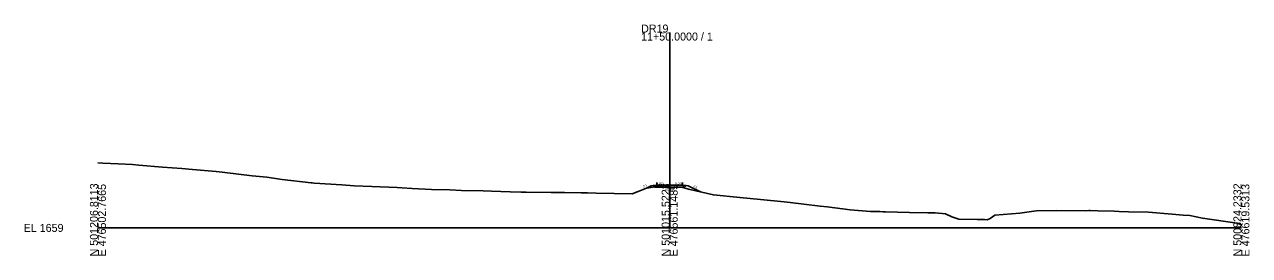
# Model space of a CAD drawing. Extents: x 79370 to 79799, y -95930 to -94349.
# Drawn here: x 79370.3 to 79798.8, y -94430.2 to -94349.2 of the extents above; entities that cross this region are included whole.
import ezdxf

# ---------------------------------------------------------------- set-up
doc = ezdxf.new("R2010")
doc.units = 0
for name, color, linetype in [('Exist Cross Section Cell', 7, 'Continuous'), ('Exist XS Center Line Elevation Label', 7, 'Continuous'), ('Exist XS Ground Line', 7, 'Continuous'), ('Prop XS Earthwork Shape', 7, 'Continuous'), ('Prop XS EOT Tick Mark', 7, 'Continuous'), ('Prop XS Finish Grade', 7, 'Continuous'), ('Prop XS Finish Grade Earthwork', 7, 'Continuous'), ('Prop XS Finish Grade Pavement', 7, 'Continuous'), ('Prop XS Pvmt Edge Slope', 7, 'Continuous'), ('Prop XS SE Text', 7, 'Continuous'), ('Prop XS Shoulder Borrow Shape', 7, 'Continuous'), ('Prop XS Side Slope Text', 7, 'Continuous'), ('Prop XS Subgrade Earthwork', 7, 'Continuous'), ('Scratch_Level_6', 7, 'Continuous')]:
    doc.layers.add(name, color=color, linetype=linetype)

msp = doc.modelspace()

# ---------------------------------------------------------------- linework, layer by layer
at = {"layer": 'Exist Cross Section Cell'}
for p, q in [((79596.01, -94420.51), (79596.01, -94352.03)), ((79396.01, -94420.51), (79596.01, -94420.51)), ((79596.01, -94420.51), (79796.01, -94420.51))]:
    msp.add_line(p, q, dxfattribs=at)
at = {"layer": 'Exist XS Ground Line'}
msp.add_lwpolyline([(79396.01, -94397.68), (79397.68, -94397.79), (79403.13, -94398.05), (79408.14, -94398.28), (79410.35, -94398.47), (79418.6, -94399.17), (79425.4, -94399.73), (79429.06, -94400), (79437.39, -94400.74), (79439.51, -94400.93), (79440.45, -94401.04), (79449.97, -94402.28), (79455.04, -94402.7), (79460.43, -94403.57), (79470.55, -94404.73), (79470.89, -94404.76), (79471.65, -94404.82), (79481.34, -94405.45), (79485.6, -94405.76), (79491.8, -94406.02), (79500.65, -94406.4), (79502.26, -94406.46), (79505.92, -94406.68), (79512.72, -94407.05), (79519.14, -94407.13), (79523.17, -94407.38), (79530.75, -94407.57), (79533.63, -94407.63), (79540.18, -94407.83), (79544.09, -94407.94), (79545.8, -94407.99), (79554.55, -94408.11), (79559.2, -94408.09), (79565, -94408.22), (79567.21, -94408.17), (79570.27, -94408.35), (79582.91, -94408.52), (79585.01, -94407.7), (79587.87, -94406.55), (79590.2, -94406.27), (79591.09, -94406.08), (79596.01, -94406.16), (79598.21, -94406.19), (79600.17, -94406.27), (79602.56, -94406.91), (79611.33, -94408.95), (79620.59, -94409.87), (79627.75, -94410.51), (79636.11, -94411.35), (79638.2, -94411.55), (79642.97, -94412.14), (79648.66, -94412.9), (79651.16, -94413.11), (79659.12, -94414.17), (79666.21, -94414.7), (79669.58, -94414.79), (79670.67, -94414.88), (79671.57, -94414.92), (79679.86, -94415.07), (79686.31, -94415.27), (79688.9, -94415.27), (79692.46, -94415.59), (79694.68, -94416.61), (79697.14, -94417.41), (79703.59, -94417.57), (79706.14, -94417.61), (79707.11, -94417.68), (79708.12, -94417.16), (79709.72, -94416.1), (79718.47, -94415.38), (79723.4, -94414.63), (79724.33, -94414.49), (79731.34, -94414.45), (79741.49, -94414.49), (79742.63, -94414.44), (79743.12, -94414.43), (79745.76, -94414.52), (79751.49, -94414.68), (79753.24, -94414.71), (79756.52, -94414.83), (79763.53, -94415.01), (79771.81, -94415.72), (79775.7, -94416), (79777.94, -94416.13), (79782.35, -94417.05), (79794.58, -94418.85), (79796.01, -94419.39)], dxfattribs=at)
at = {"layer": 'Prop XS Earthwork Shape'}
for points in [[(79590.72, -94406.16), (79590.25, -94405.69), (79589.51, -94405.74), (79587.87, -94406.55), (79590.2, -94406.27)], [(79589.51, -94405.74), (79587.87, -94406.55), (79590.2, -94406.27), (79590.72, -94406.16), (79590.25, -94405.69)], [(79600.51, -94406.25), (79601.19, -94406.27), (79601.77, -94405.69), (79602.51, -94405.74), (79606.82, -94407.9), (79602.56, -94406.91), (79600.17, -94406.27), (79599.77, -94406.25)], [(79602.51, -94405.74), (79606.82, -94407.9), (79602.56, -94406.91), (79600.17, -94406.27), (79600.17, -94406.24), (79600.51, -94406.25), (79601.19, -94406.27), (79601.77, -94405.69)], [(79590.72, -94406.16), (79591.09, -94406.08), (79591.51, -94406.08), (79591.51, -94406.25), (79590.83, -94406.27)], [(79590.83, -94406.27), (79590.72, -94406.16), (79591.09, -94406.08), (79596.01, -94406.16), (79598.21, -94406.19), (79599.77, -94406.25), (79591.51, -94406.25)]]:
    msp.add_lwpolyline(points, close=True, dxfattribs=at)
at = {"layer": 'Prop XS EOT Tick Mark'}
for p, q in [((79591.51, -94405.58), (79591.51, -94404.58)), ((79600.51, -94405.58), (79600.51, -94404.58))]:
    msp.add_line(p, q, dxfattribs=at)
at = {"layer": 'Prop XS Finish Grade'}
for p, q in [((79591.51, -94405.58), (79590.25, -94405.69)), ((79600.51, -94405.58), (79601.77, -94405.69))]:
    msp.add_line(p, q, dxfattribs=at)
at = {"layer": 'Prop XS Finish Grade Earthwork'}
for p, q in [((79590.25, -94405.69), (79589.51, -94405.74)), ((79601.77, -94405.69), (79602.51, -94405.74)), ((79589.51, -94405.74), (79587.87, -94406.55)), ((79602.51, -94405.74), (79606.82, -94407.9))]:
    msp.add_line(p, q, dxfattribs=at)
at = {"layer": 'Prop XS Finish Grade Pavement'}
for p, q in [((79591.51, -94405.58), (79596.01, -94405.49)), ((79596.01, -94405.49), (79600.51, -94405.58))]:
    msp.add_line(p, q, dxfattribs=at)
at = {"layer": 'Prop XS Pvmt Edge Slope'}
for p, q in [((79591.51, -94405.58), (79590.83, -94406.27)), ((79600.51, -94405.58), (79601.19, -94406.27))]:
    msp.add_line(p, q, dxfattribs=at)
at = {"layer": 'Prop XS Shoulder Borrow Shape'}
for points in [[(79591.51, -94405.58), (79590.83, -94406.27), (79590.25, -94405.69)], [(79601.19, -94406.27), (79601.77, -94405.69), (79600.51, -94405.58)]]:
    msp.add_lwpolyline(points, close=True, dxfattribs=at)
at = {"layer": 'Prop XS Subgrade Earthwork'}
for p, q in [((79590.83, -94406.27), (79590.25, -94405.69)), ((79601.19, -94406.27), (79601.77, -94405.69)), ((79591.51, -94406.25), (79590.83, -94406.27)), ((79600.51, -94406.25), (79591.51, -94406.25)), ((79600.51, -94406.25), (79601.19, -94406.27))]:
    msp.add_line(p, q, dxfattribs=at)
at = {"layer": 'Scratch_Level_6'}
msp.add_line((79591.51, -94406.08), (79600.17, -94406.27), dxfattribs=at)

# ---------------------------------------------------------------- texts
at = {"layer": 'Exist Cross Section Cell'}
for s, p in [('DR19', (79586.01, -94352.03)), ('11+50.0000 / 1', (79586.01, -94354.83)), ('EL 1659', (79370.01, -94421.91))]:
    msp.add_text(s, height=2.8, dxfattribs=at).set_placement(p)
for s, p in [('N 501206.8113', (79396.01, -94430.51)), ('E 476502.7665', (79398.81, -94430.51)), ('N 501015.5223', (79596.01, -94430.51)), ('E 476561.1489', (79598.81, -94430.51)), ('N 500824.2332', (79796.01, -94430.51)), ('E 476619.5313', (79798.81, -94430.51))]:
    msp.add_text(s, height=2.8, rotation=90, dxfattribs=at).set_placement(p)
at = {"layer": 'Exist XS Center Line Elevation Label'}
msp.add_text('1673.35', height=0.75, dxfattribs=at).set_placement((79594.22, -94407.41))
at = {"layer": 'Prop XS SE Text'}
for rotation, p in [(1.1458, (79591.35, -94405.27)), (358.8542, (79597.95, -94405.26))]:
    msp.add_text('0.020', height=0.75, rotation=rotation, dxfattribs=at).set_placement(p)
at = {"layer": 'Prop XS Side Slope Text'}
for rotation, p in [(26.5651, (79586.89, -94406.4)), (333.4349, (79604.26, -94406.08))]:
    msp.add_text('2:1', height=0.75, rotation=rotation, dxfattribs=at).set_placement(p)

doc.saveas('drawing.dxf')
